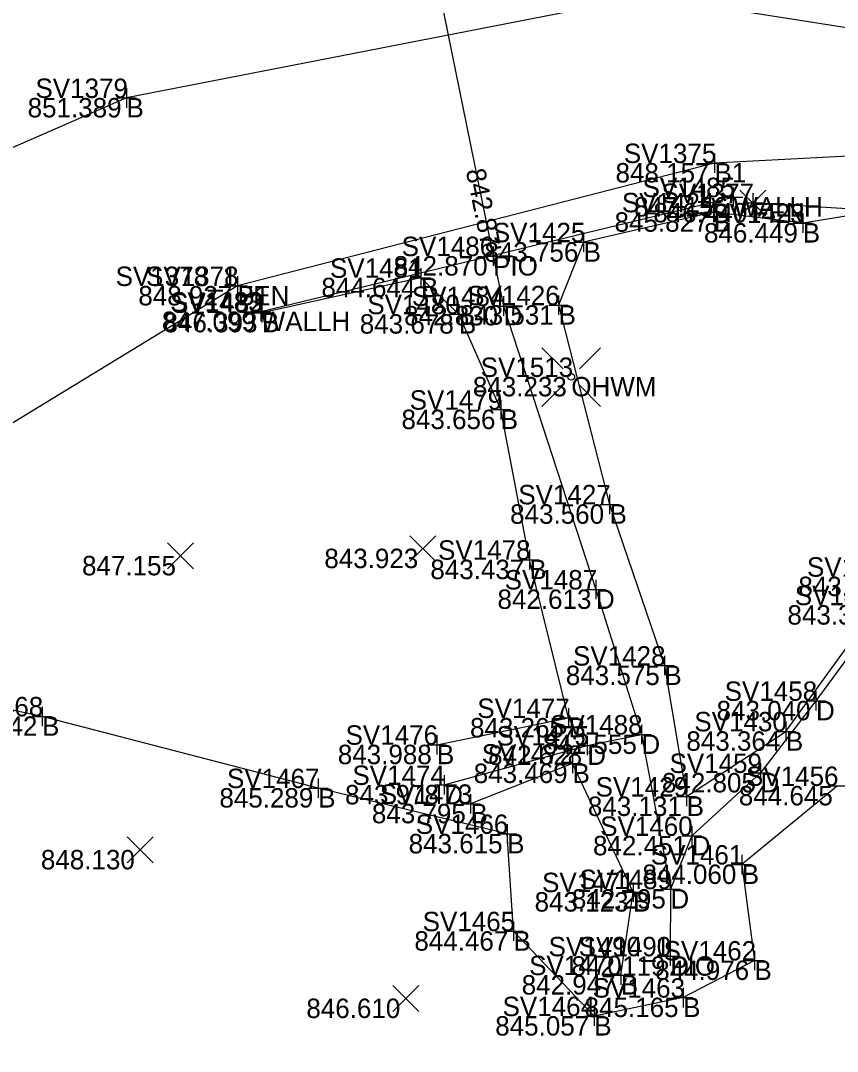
# Model space of a CAD drawing. Extents: x 2125299 to 2129212, y 713100 to 714300.
# Drawn here: x 2128313.4 to 2128355.4, y 713842.2 to 713895.2 of the extents above; entities that cross this region are included whole.
import ezdxf

# ---------------------------------------------------------------- set-up
doc = ezdxf.new("R2010")
doc.units = 0
for name, color, linetype in [('DR_X_Ditch', 7, 'Continuous'), ('DR_X_Headwall', 7, 'Continuous'), ('DR_X_Storm_Sewer', 7, 'Continuous'), ('RD_X_Fence', 7, 'Continuous'), ('RW_P_Esmt_TMP', 7, 'Continuous'), ('RW_X_CL_100_Cardinal_Points', 7, 'Continuous'), ('RW_X_Esmt_CH', 7, 'Continuous'), ('RW_X_Fee_WL', 7, 'Continuous'), ('SC_Scratch1', 7, 'Continuous'), ('SV_X_Break_Lines', 7, 'Continuous'), ('SV_X_Mon_Cells_Found', 7, 'Continuous'), ('SV_X_Text_Elevation', 7, 'Continuous'), ('SV_X_Text_Name', 7, 'Continuous')]:
    doc.layers.add(name, color=color, linetype=linetype)

msp = doc.modelspace()

# ---------------------------------------------------------------- linework, layer by layer
at = {"layer": 'DR_X_Ditch'}
for points in [[(2128337.681, 713883.118), (2128338.221, 713880.548), (2128342.972, 713865.958), (2128345.313, 713858.492), (2128346.806, 713850.533), (2128346.799, 713847.076)], [(2128380.672, 713870.195), (2128372.514, 713869.076), (2128365.668, 713866.704), (2128361.997, 713866.06), (2128357.9, 713865.15), (2128354.295, 713860.223), (2128351.441, 713856.512), (2128347.904, 713853.274), (2128346.806, 713850.533)], [(2128335.165, 713855.896), (2128342.529, 713857.927), (2128345.313, 713858.492)]]:
    msp.add_lwpolyline(points, dxfattribs=at)
at = {"layer": 'DR_X_Headwall'}
msp.add_lwpolyline([(2128325.727, 713880.262), (2128350.038, 713886.154)], dxfattribs=at)
at = {"layer": 'DR_X_Storm_Sewer'}
msp.add_line((2128282.878, 714152.985), (2128337.681, 713883.118), dxfattribs=at)
at = {"layer": 'RD_X_Fence'}
for points in [[(2128620.57, 713921.414), (2128582.003, 713911.258), (2128527.9, 713897.049), (2128485.218, 713885.694), (2128444.136, 713879.079), (2128410.256, 713882.079), (2128351.04, 713885.853)], [(2128324.526, 713881.58), (2128301.553, 713867.571), (2128272.196, 713849.199), (2128249.081, 713832.867), (2128213.094, 713823.853), (2128180.679, 713818.154), (2128133.829, 713809.764), (2128103.722, 713804.695), (2128050.486, 713795.434)]]:
    msp.add_lwpolyline(points, dxfattribs=at)
at = {"layer": 'RW_X_CL_100_Cardinal_Points'}
for p, q in [((2128337.681, 713883.618), (2128337.681, 713882.618)), ((2128337.181, 713883.118), (2128338.181, 713883.118)), ((2128337.681, 713883.118), (2128337.681, 713883.118)), ((2128346.799, 713847.576), (2128346.799, 713846.576)), ((2128346.299, 713847.076), (2128347.299, 713847.076)), ((2128346.799, 713847.076), (2128346.799, 713847.076))]:
    msp.add_line(p, q, dxfattribs=at)
at = {"layer": 'SV_X_Break_Lines'}
for p, q in [((2128344.882, 713850.377), (2128344.882, 713850.377)), ((2128344.249, 713846.105), (2128344.249, 713846.105))]:
    msp.add_line(p, q, dxfattribs=at)
for points in [[(2128473.365, 713923.912), (2128453.453, 713915.843), (2128410.188, 713893.98), (2128387.409, 713892.535), (2128363.211, 713893.719), (2128345.595, 713896.5), (2128318.819, 713891.258), (2128295.116, 713880.906), (2128274.488, 713885.799), (2128242.12, 713879.196), (2128218.829, 713874.939), (2128184.367, 713862.099), (2128151.548, 713852.787), (2128121.592, 713848.655), (2128121.634, 713848.486), (2128085.287, 713843.491), (2128066.442, 713838.356)], [(2128362.17, 713888.596), (2128349.078, 713887.908), (2128324.526, 713881.58), (2128301.553, 713867.571), (2128295.426, 713864.02), (2128280.273, 713864.928), (2128247.092, 713854.317), (2128208.777, 713841.528), (2128155.39, 713832.168), (2128105.372, 713824.737)], [(2128364.108, 713886.51), (2128353.616, 713884.817), (2128349.029, 713885.373), (2128342.339, 713883.832), (2128341.051, 713880.59), (2128343.672, 713870.34), (2128346.494, 713862.039), (2128347.64, 713855.299), (2128352.748, 713858.655), (2128358.51, 713866.616)], [(2128334.793, 713857.965), (2128341.564, 713859.343), (2128339.549, 713867.49), (2128338.073, 713875.214), (2128335.923, 713880.129), (2128333.972, 713882.002), (2128325.79, 713880.196)], [(2128355.396, 713855.844), (2128350.477, 713851.799), (2128351.127, 713846.858), (2128347.461, 713844.948), (2128342.888, 713843.995), (2128338.728, 713848.366), (2128338.407, 713853.375), (2128328.685, 713855.732), (2128314.478, 713859.425), (2128303.528, 713861.756)], [(2128344.249, 713846.105), (2128344.882, 713850.377), (2128341.77, 713856.994), (2128336.516, 713854.923)]]:
    msp.add_lwpolyline(points, dxfattribs=at)
at = {"layer": 'SV_X_Mon_Cells_Found'}
for p, q in [((2128318.819, 713891.758), (2128318.819, 713890.758)), ((2128318.319, 713891.258), (2128319.319, 713891.258)), ((2128318.819, 713891.258), (2128318.819, 713891.258)), ((2128349.078, 713888.408), (2128349.078, 713887.408)), ((2128348.578, 713887.908), (2128349.578, 713887.908)), ((2128349.078, 713887.908), (2128349.078, 713887.908)), ((2128350.038, 713886.654), (2128350.038, 713885.654)), ((2128349.029, 713885.873), (2128349.029, 713884.873)), ((2128349.538, 713886.154), (2128350.538, 713886.154)), ((2128350.038, 713886.154), (2128350.038, 713886.154)), ((2128351.04, 713886.353), (2128351.04, 713885.353)), ((2128348.529, 713885.373), (2128349.529, 713885.373)), ((2128349.029, 713885.373), (2128349.029, 713885.373)), ((2128350.54, 713885.853), (2128351.54, 713885.853)), ((2128351.04, 713885.853), (2128351.04, 713885.853)), ((2128353.116, 713884.817), (2128354.116, 713884.817)), ((2128353.616, 713885.317), (2128353.616, 713884.317)), ((2128353.616, 713884.817), (2128353.616, 713884.817)), ((2128342.339, 713884.332), (2128342.339, 713883.332)), ((2128341.839, 713883.832), (2128342.839, 713883.832)), ((2128342.339, 713883.832), (2128342.339, 713883.832)), ((2128333.972, 713882.502), (2128333.972, 713881.502)), ((2128324.526, 713882.08), (2128324.526, 713881.08)), ((2128324.526, 713882.08), (2128324.526, 713881.08)), ((2128333.472, 713882.002), (2128334.472, 713882.002)), ((2128333.972, 713882.002), (2128333.972, 713882.002)), ((2128324.026, 713881.58), (2128325.026, 713881.58)), ((2128324.026, 713881.58), (2128325.026, 713881.58)), ((2128324.526, 713881.58), (2128324.526, 713881.58)), ((2128324.526, 713881.58), (2128324.526, 713881.58)), ((2128325.727, 713880.762), (2128325.727, 713879.762)), ((2128325.79, 713880.696), (2128325.79, 713879.696)), ((2128335.923, 713880.629), (2128335.923, 713879.629)), ((2128338.221, 713881.048), (2128338.221, 713880.048)), ((2128340.551, 713880.59), (2128341.551, 713880.59)), ((2128341.051, 713881.09), (2128341.051, 713880.09)), ((2128341.051, 713880.59), (2128341.051, 713880.59)), ((2128325.227, 713880.262), (2128326.227, 713880.262)), ((2128325.29, 713880.196), (2128326.29, 713880.196)), ((2128325.727, 713880.262), (2128325.727, 713880.262)), ((2128325.79, 713880.196), (2128325.79, 713880.196)), ((2128335.423, 713880.129), (2128336.423, 713880.129)), ((2128335.923, 713880.129), (2128335.923, 713880.129)), ((2128337.721, 713880.548), (2128338.721, 713880.548)), ((2128338.221, 713880.548), (2128338.221, 713880.548)), ((2128338.073, 713875.714), (2128338.073, 713874.714)), ((2128337.573, 713875.214), (2128338.573, 713875.214)), ((2128338.073, 713875.214), (2128338.073, 713875.214)), ((2128343.672, 713870.84), (2128343.672, 713869.84)), ((2128343.172, 713870.34), (2128344.172, 713870.34)), ((2128343.672, 713870.34), (2128343.672, 713870.34)), ((2128339.549, 713867.99), (2128339.549, 713866.99)), ((2128339.049, 713867.49), (2128340.049, 713867.49)), ((2128339.549, 713867.49), (2128339.549, 713867.49)), ((2128342.972, 713866.458), (2128342.972, 713865.458)), ((2128342.472, 713865.958), (2128343.472, 713865.958)), ((2128342.972, 713865.958), (2128342.972, 713865.958)), ((2128346.494, 713862.539), (2128346.494, 713861.539)), ((2128345.994, 713862.039), (2128346.994, 713862.039)), ((2128346.494, 713862.039), (2128346.494, 713862.039)), ((2128354.295, 713860.723), (2128354.295, 713859.723)), ((2128314.478, 713859.925), (2128314.478, 713858.925)), ((2128353.795, 713860.223), (2128354.795, 713860.223)), ((2128354.295, 713860.223), (2128354.295, 713860.223)), ((2128313.978, 713859.425), (2128314.978, 713859.425)), ((2128314.478, 713859.425), (2128314.478, 713859.425)), ((2128341.064, 713859.343), (2128342.064, 713859.343)), ((2128341.564, 713859.843), (2128341.564, 713858.843)), ((2128341.564, 713859.343), (2128341.564, 713859.343)), ((2128345.313, 713858.992), (2128345.313, 713857.992)), ((2128352.748, 713859.155), (2128352.748, 713858.155)), ((2128334.793, 713858.465), (2128334.793, 713857.465)), ((2128342.529, 713858.427), (2128342.529, 713857.427)), ((2128344.813, 713858.492), (2128345.813, 713858.492)), ((2128345.313, 713858.492), (2128345.313, 713858.492)), ((2128352.248, 713858.655), (2128353.248, 713858.655)), ((2128352.748, 713858.655), (2128352.748, 713858.655)), ((2128334.293, 713857.965), (2128335.293, 713857.965)), ((2128334.793, 713857.965), (2128334.793, 713857.965)), ((2128342.029, 713857.927), (2128343.029, 713857.927)), ((2128342.529, 713857.927), (2128342.529, 713857.927)), ((2128341.77, 713857.494), (2128341.77, 713856.494)), ((2128341.27, 713856.994), (2128342.27, 713856.994)), ((2128341.77, 713856.994), (2128341.77, 713856.994)), ((2128351.441, 713857.012), (2128351.441, 713856.012)), ((2128328.685, 713856.232), (2128328.685, 713855.232)), ((2128335.165, 713856.396), (2128335.165, 713855.396)), ((2128350.941, 713856.512), (2128351.941, 713856.512)), ((2128351.441, 713856.512), (2128351.441, 713856.512)), ((2128328.185, 713855.732), (2128329.185, 713855.732)), ((2128328.685, 713855.732), (2128328.685, 713855.732)), ((2128334.665, 713855.896), (2128335.665, 713855.896)), ((2128335.165, 713855.896), (2128335.165, 713855.896)), ((2128347.64, 713855.799), (2128347.64, 713854.799)), ((2128354.896, 713855.844), (2128355.896, 713855.844)), ((2128336.516, 713855.423), (2128336.516, 713854.423)), ((2128347.14, 713855.299), (2128348.14, 713855.299)), ((2128347.64, 713855.299), (2128347.64, 713855.299)), ((2128336.016, 713854.923), (2128337.016, 713854.923)), ((2128336.516, 713854.923), (2128336.516, 713854.923)), ((2128338.407, 713853.875), (2128338.407, 713852.875)), ((2128347.904, 713853.774), (2128347.904, 713852.774)), ((2128337.907, 713853.375), (2128338.907, 713853.375)), ((2128338.407, 713853.375), (2128338.407, 713853.375)), ((2128347.404, 713853.274), (2128348.404, 713853.274)), ((2128347.904, 713853.274), (2128347.904, 713853.274)), ((2128350.477, 713852.299), (2128350.477, 713851.299)), ((2128349.977, 713851.799), (2128350.977, 713851.799)), ((2128350.477, 713851.799), (2128350.477, 713851.799)), ((2128344.882, 713850.877), (2128344.882, 713849.877)), ((2128346.806, 713851.033), (2128346.806, 713850.033)), ((2128344.382, 713850.377), (2128345.382, 713850.377)), ((2128344.882, 713850.377), (2128344.882, 713850.377)), ((2128346.306, 713850.533), (2128347.306, 713850.533)), ((2128346.806, 713850.533), (2128346.806, 713850.533)), ((2128338.728, 713848.866), (2128338.728, 713847.866)), ((2128338.228, 713848.366), (2128339.228, 713848.366)), ((2128338.728, 713848.366), (2128338.728, 713848.366)), ((2128346.799, 713847.576), (2128346.799, 713846.576)), ((2128351.127, 713847.358), (2128351.127, 713846.358)), ((2128344.249, 713846.605), (2128344.249, 713845.605)), ((2128346.299, 713847.076), (2128347.299, 713847.076)), ((2128346.799, 713847.076), (2128346.799, 713847.076)), ((2128350.627, 713846.858), (2128351.627, 713846.858)), ((2128351.127, 713846.858), (2128351.127, 713846.858)), ((2128343.749, 713846.105), (2128344.749, 713846.105)), ((2128344.249, 713846.105), (2128344.249, 713846.105)), ((2128347.461, 713845.448), (2128347.461, 713844.448)), ((2128342.888, 713844.495), (2128342.888, 713843.495)), ((2128346.961, 713844.948), (2128347.961, 713844.948)), ((2128347.461, 713844.948), (2128347.461, 713844.948)), ((2128342.388, 713843.995), (2128343.388, 713843.995)), ((2128342.888, 713843.995), (2128342.888, 713843.995))]:
    msp.add_line(p, q, dxfattribs=at)
at = {"layer": 'SV_X_Text_Elevation'}
for p, q in [((2128350.373, 713885.185), (2128351.707, 713886.52)), ((2128350.373, 713886.52), (2128351.707, 713885.185)), ((2128333.396, 713867.39), (2128334.73, 713868.725)), ((2128333.396, 713868.725), (2128334.73, 713867.39)), ((2128320.936, 713867.019), (2128322.27, 713868.354)), ((2128320.936, 713868.354), (2128322.27, 713867.019)), ((2128318.864, 713851.883), (2128320.198, 713853.218)), ((2128318.864, 713853.218), (2128320.198, 713851.883)), ((2128332.521, 713844.229), (2128333.855, 713845.564)), ((2128332.521, 713845.564), (2128333.855, 713844.229))]:
    msp.add_line(p, q, dxfattribs=at)
at = {"layer": 'SV_X_Text_Name'}
for p, q in [((2128340.196, 713878.402), (2128341.289, 713877.308)), ((2128342.123, 713877.308), (2128343.214, 713878.402)), ((2128340.196, 713875.383), (2128341.289, 713876.477)), ((2128342.123, 713876.477), (2128343.214, 713875.383))]:
    msp.add_line(p, q, dxfattribs=at)
msp.add_circle((2128341.706, 713876.898), 0.17, dxfattribs=at)

# ---------------------------------------------------------------- texts
at = {"layer": 'RW_P_Esmt_TMP'}
for s, p in [('B', (2128318.819, 713890.258)), ('B1', (2128349.078, 713886.908)), ('WALLH', (2128350.038, 713885.154)), ('B', (2128349.029, 713884.373)), ('FEN', (2128351.04, 713884.853)), ('B', (2128353.616, 713883.817)), ('B', (2128342.339, 713882.832)), ('PIO', (2128337.681, 713882.118)), ('B', (2128333.972, 713881.002)), ('B1', (2128324.526, 713880.58)), ('FEN', (2128324.526, 713880.58)), ('B', (2128341.051, 713879.59)), ('WALLH', (2128325.727, 713879.262)), ('B', (2128325.79, 713879.196)), ('B', (2128335.923, 713879.129)), ('D', (2128338.221, 713879.548)), ('OHWM', (2128341.706, 713875.898)), ('B', (2128338.073, 713874.214)), ('B', (2128343.672, 713869.34)), ('B', (2128339.549, 713866.49)), ('D', (2128342.972, 713864.958)), ('B', (2128346.494, 713861.039)), ('D', (2128354.295, 713859.223)), ('B', (2128314.478, 713858.425)), ('B', (2128341.564, 713858.343)), ('D', (2128345.313, 713857.492)), ('B', (2128352.748, 713857.655)), ('B', (2128334.793, 713856.965)), ('D', (2128342.529, 713856.927)), ('B', (2128341.77, 713855.994)), ('D', (2128351.441, 713855.512)), ('B', (2128328.685, 713854.732)), ('D', (2128335.165, 713854.896)), ('B', (2128347.64, 713854.299)), ('B', (2128336.516, 713853.923)), ('B', (2128338.407, 713852.375)), ('D', (2128347.904, 713852.274)), ('B', (2128350.477, 713850.799)), ('B', (2128344.882, 713849.377)), ('D', (2128346.806, 713849.533)), ('B', (2128338.728, 713847.366)), ('PIO', (2128346.799, 713846.076)), ('D', (2128346.799, 713846.076)), ('B', (2128351.127, 713845.858)), ('B', (2128344.249, 713845.105)), ('B', (2128347.461, 713843.948)), ('B', (2128342.888, 713842.995))]:
    msp.add_text(s, height=1, dxfattribs=at).set_placement(p)
at = {"layer": 'RW_X_Esmt_CH'}
for s, p in [('SV1379', (2128314.137, 713891.258)), ('SV1375', (2128344.409, 713887.908)), ('SV1485', (2128345.369, 713886.154)), ('SV1377', (2128346.346, 713885.853)), ('SV1424', (2128344.309, 713885.373)), ('SV1423', (2128348.954, 713884.817)), ('SV1425', (2128337.67, 713883.832)), ('SV1486', (2128332.979, 713883.118)), ('SV1481', (2128329.292, 713882.002)), ('SV1378_1', (2128318.263, 713881.58)), ('SV1378', (2128319.827, 713881.58)), ('SV1483', (2128321.065, 713880.262)), ('SV1482', (2128321.119, 713880.196)), ('SV1480', (2128331.211, 713880.129)), ('SV1484', (2128333.501, 713880.548)), ('SV1426', (2128336.349, 713880.59)), ('SV1513', (2128337.044, 713876.898)), ('SV1479', (2128333.391, 713875.214)), ('SV1427', (2128338.978, 713870.34)), ('SV1478', (2128334.85, 713867.49)), ('SV1431', (2128353.83, 713866.616)), ('SV1487', (2128338.278, 713865.958)), ('SV1457', (2128353.206, 713865.15)), ('SV1428', (2128341.795, 713862.039)), ('SV1458', (2128349.596, 713860.223)), ('SV1468', (2128309.779, 713859.425)), ('SV1477', (2128336.87, 713859.343)), ('SV1488', (2128340.614, 713858.492)), ('SV1430', (2128348.036, 713858.655)), ('SV1476', (2128330.091, 713857.965)), ('SV1475', (2128337.86, 713857.927)), ('SV1472', (2128337.099, 713856.994)), ('SV1459', (2128346.759, 713856.512)), ('SV1467', (2128323.991, 713855.732)), ('SV1474', (2128330.445, 713855.896)), ('SV1456', (2128350.694, 713855.844)), ('SV1429', (2128342.958, 713855.299)), ('SV1473', (2128331.854, 713854.923)), ('SV1466', (2128333.705, 713853.375)), ('SV1460', (2128343.192, 713853.274)), ('SV1461', (2128345.797, 713851.799)), ('SV1471', (2128340.202, 713850.377)), ('SV1489', (2128342.124, 713850.533)), ('SV1465', (2128334.059, 713848.366)), ('SV1490_1', (2128340.536, 713847.076)), ('SV1490', (2128342.087, 713847.076)), ('SV1462', (2128346.456, 713846.858)), ('SV1470', (2128339.537, 713846.105)), ('SV1463', (2128342.799, 713844.948)), ('SV1464', (2128338.168, 713843.995))]:
    msp.add_text(s, height=1, dxfattribs=at).set_placement(p)
at = {"layer": 'RW_X_Fee_WL'}
for s, p in [('851.389', (2128313.735, 713890.258)), ('848.157', (2128343.982, 713886.908)), ('847.156', (2128344.934, 713885.154)), ('845.827', (2128343.933, 713884.373)), ('846.440', (2128345.926, 713884.853)), ('846.440', (2128345.926, 713884.853)), ('846.449', (2128348.532, 713883.817)), ('843.756', (2128337.235, 713882.832)), ('842.870', (2128332.567, 713882.118)), ('844.644', (2128328.85, 713881.002)), ('848.927', (2128319.43, 713880.58)), ('848.927', (2128319.43, 713880.58)), ('842.830', (2128333.107, 713879.548)), ('843.531', (2128335.969, 713879.59)), ('847.099', (2128320.643, 713879.262)), ('846.393', (2128320.727, 713879.196)), ('843.678', (2128330.823, 713879.129)), ('843.233', (2128336.642, 713875.898)), ('843.656', (2128332.969, 713874.214)), ('843.560', (2128338.558, 713869.34)), ('843.923', (2128328.999, 713867.057)), ('847.155', (2128316.533, 713866.686)), ('843.437', (2128334.453, 713866.49)), ('843.964', (2128353.388, 713865.616)), ('842.613', (2128337.908, 713864.958)), ('843.332', (2128352.827, 713864.15)), ('843.575', (2128341.424, 713861.039)), ('843.040', (2128349.181, 713859.223)), ('847.842', (2128309.405, 713858.425)), ('843.265', (2128336.494, 713858.343)), ('842.555', (2128340.243, 713857.492)), ('843.364', (2128347.626, 713857.655)), ('843.988', (2128329.693, 713856.965)), ('842.628', (2128337.429, 713856.927)), ('843.469', (2128336.686, 713855.994)), ('842.805', (2128346.371, 713855.512)), ('845.289', (2128323.601, 713854.732)), ('843.978', (2128330.065, 713854.896)), ('844.645', (2128350.326, 713854.844)), ('843.131', (2128342.558, 713854.299)), ('843.795', (2128331.446, 713853.923)), ('843.615', (2128333.337, 713852.375)), ('842.451', (2128342.822, 713852.274)), ('848.130', (2128314.417, 713851.551)), ('844.060', (2128345.363, 713850.799)), ('843.123', (2128339.818, 713849.377)), ('842.295', (2128341.736, 713849.533)), ('844.467', (2128333.632, 713847.366)), ('842.119', (2128341.715, 713846.076)), ('842.119', (2128341.715, 713846.076)), ('844.976', (2128346.023, 713845.858)), ('842.947', (2128339.153, 713845.105)), ('846.610', (2128328.074, 713843.897)), ('845.165', (2128342.391, 713843.948)), ('845.057', (2128337.792, 713842.995))]:
    msp.add_text(s, height=1, dxfattribs=at).set_placement(p)
at = {"layer": 'SC_Scratch1'}
msp.add_text("842.87'", height=1, rotation=281.4792, dxfattribs=at).set_placement((2128336.276, 713887.525))

doc.saveas('drawing.dxf')
